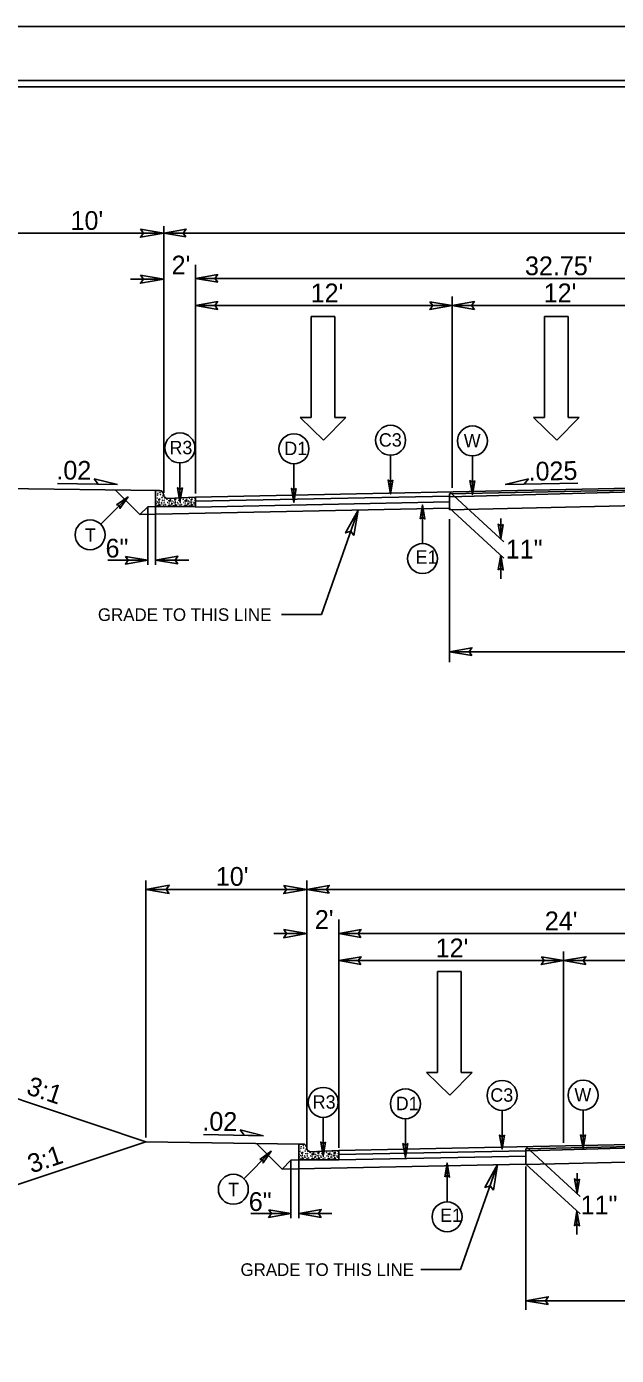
# Model space of a CAD drawing. Extents: x 958711 to 962106, y 831169 to 840840.
# Drawn here: x 959156 to 959402, y 839063 to 839615 of the extents above; entities that cross this region are included whole.
import ezdxf

# ---------------------------------------------------------------- set-up
doc = ezdxf.new("R2010")
doc.units = 0
for name, color, linetype in [('Old_Level_1', 7, 'Continuous'), ('Old_Level_11', 7, 'Continuous'), ('Old_Level_3', 7, 'Continuous'), ('Prop Dimension Text', 7, 'Continuous'), ('Prop Lane Arrow CELL', 7, 'Continuous'), ('Sheet Plot Border Inside CELL', 7, 'Continuous'), ('Sheet Plot Border Outside CELL', 7, 'Continuous'), ('Sheet Typical CELL', 7, 'Continuous'), ('Typical ID Circle CELL', 7, 'Continuous'), ('Typical Terminator CELL', 7, 'Continuous'), ('Typical Text ID Circle CELL', 7, 'Continuous')]:
    doc.layers.add(name, color=color, linetype=linetype)

# ---------------------------------------------------------------- blocks, each defined once
blk = doc.blocks.new('Lane Arrow Through')
at = {"layer": 'Prop Lane Arrow CELL'}
for p, q in [((-3.15, 1.6), (-3.15, 3.1)), ((-3.15, 3.1), (0, 0)), ((-17.15, 1.6), (-3.15, 1.6)), ((-17.15, -1.7), (-17.15, 1.6)), ((0, 0), (-3.15, -3.2)), ((-3.15, -1.7), (-17.15, -1.7)), ((-3.15, -3.2), (-3.15, -1.7))]:
    blk.add_line(p, q, dxfattribs=at)

msp = doc.modelspace()

# ---------------------------------------------------------------- linework, layer by layer
at = {"layer": 'Old_Level_1'}
for p, q in [((959146.5, 839529.55), (959213.41, 839529.55)), ((959213.41, 839421.58), (959213.41, 839532.49)), ((959213.41, 839529.55), (959779.86, 839529.55)), ((959226.62, 839421.34), (959226.62, 839516.32)), ((959199.59, 839510.4), (959213.41, 839510.4)), ((959226.62, 839510.66), (959494.95, 839510.66)), ((959333.31, 839423.65), (959333.31, 839503.17)), ((959226.62, 839499.42), (959333.31, 839499.42)), ((959333.31, 839499.42), (959426.79, 839499.42)), ((959146.5, 839423.43), (959210.34, 839422.49)), ((959169.25, 839425.52), (959194.22, 839425.02)), ((959203.5, 839412.54), (959193.39, 839422.65)), ((959494.95, 839425.26), (959226.62, 839419.83)), ((959494.95, 839424.4), (959332.23, 839419.96)), ((959494.94, 839424.4), (959332.23, 839421.1)), ((959385.49, 839425.61), (959355.28, 839425)), ((959332.23, 839420.24), (959226.62, 839418.11)), ((959332.23, 839417.81), (959226.62, 839415.68)), ((959332.23, 839421.97), (959354.74, 839401.25)), ((959332.23, 839419.96), (959332.23, 839421.1)), ((959332.23, 839419.96), (959332.23, 839414.51)), ((959206.75, 839415.78), (959203.5, 839412.54)), ((959332.23, 839415.14), (959203.5, 839412.54)), ((959210.05, 839415.85), (959206.75, 839415.78)), ((959206.75, 839391.63), (959206.75, 839415.59)), ((959210.05, 839391.63), (959210.05, 839415.59)), ((959278.98, 839371.05), (959294.19, 839414.37)), ((959332.23, 839415.14), (959354.74, 839394.43)), ((959332.23, 839410.67), (959332.23, 839351.24)), ((959353.47, 839410.92), (959353.47, 839402.42)), ((959353.47, 839395.6), (959353.47, 839385.82)), ((959190.15, 839393.59), (959206.75, 839393.59)), ((959210.05, 839393.59), (959223.78, 839393.59)), ((959262.36, 839371.05), (959278.98, 839371.05)), ((959332.23, 839355.52), (959653.23, 839355.52)), ((959206.03, 839153.57), (959206.03, 839260.43)), ((959272.95, 839149.54), (959272.95, 839260.46)), ((959206.03, 839256.74), (959272.95, 839256.74)), ((959272.95, 839256.74), (959716.13, 839256.74)), ((959286.16, 839149.31), (959286.16, 839244.28)), ((959259.12, 839238.36), (959272.95, 839238.36)), ((959286.16, 839238.36), (959473.12, 839238.36)), ((959379.64, 839151.35), (959379.64, 839230.87)), ((959286.16, 839227.12), (959379.64, 839227.12)), ((959379.64, 839227.12), (959473.12, 839227.12)), ((959206.03, 839151.83), (959128.85, 839177.56)), ((959229.94, 839154.84), (959254.92, 839154.34)), ((959473.12, 839152.01), (959286.16, 839148.23)), ((959128.85, 839126.1), (959206.03, 839151.83)), ((959206.03, 839151.83), (959269.87, 839150.89)), ((959262.59, 839140.5), (959251.94, 839151.15)), ((959363.95, 839148.08), (959286.16, 839146.51)), ((959494.54, 839151.58), (959363.95, 839148.03)), ((959473.12, 839151.15), (959363.95, 839148.94)), ((959363.95, 839149.81), (959386.46, 839129.09)), ((959363.95, 839148.03), (959363.95, 839148.94)), ((959363.95, 839148.03), (959363.95, 839142.42)), ((959266.28, 839144.18), (959262.59, 839140.5)), ((959363.95, 839142.55), (959262.59, 839140.5)), ((959269.58, 839144.25), (959266.28, 839144.18)), ((959266.28, 839120.03), (959266.28, 839143.99)), ((959269.58, 839120.03), (959269.58, 839143.99)), ((959363.95, 839145.83), (959286.16, 839144.25)), ((959336.83, 839098.75), (959352.13, 839142.31)), ((959363.95, 839142.55), (959386.46, 839121.83)), ((959363.95, 839141.5), (959363.95, 839082)), ((959385.2, 839138.76), (959385.2, 839130.26)), ((959249.68, 839121.99), (959266.28, 839121.99)), ((959269.58, 839121.99), (959283.31, 839121.99)), ((959385.18, 839123.01), (959385.19, 839113.23)), ((959320.22, 839098.75), (959336.83, 839098.75)), ((959363.95, 839085.77), (959622.89, 839085.77))]:
    msp.add_line(p, q, dxfattribs=at)
for points in [[(959332.23, 839414.51), (959494.95, 839418.21)], [(959363.95, 839142.42), (959494.7, 839145.4)]]:
    msp.add_lwpolyline(points, dxfattribs=at)
at = {"layer": 'Old_Level_11'}
for p, q in [((959186.22, 839425.18), (959184.49, 839427.43)), ((959184.49, 839427.43), (959194.22, 839425.02)), ((959194.22, 839425.02), (959186.22, 839425.18)), ((959355.28, 839425), (959365.04, 839427.43)), ((959363.3, 839425.16), (959355.28, 839425)), ((959365.04, 839427.43), (959363.3, 839425.16)), ((959246.91, 839154.5), (959245.18, 839156.75)), ((959245.18, 839156.75), (959254.92, 839154.34)), ((959254.92, 839154.34), (959246.91, 839154.5))]:
    msp.add_line(p, q, dxfattribs=at)
for points in [[(959203.81, 839531.21), (959213.41, 839529.55), (959203.75, 839527.84), (959204.98, 839529.55)], [(959203.81, 839512.05), (959213.41, 839510.4), (959203.75, 839508.68), (959204.98, 839510.4)], [(959292.49, 839403.78), (959294.19, 839414.37), (959288.98, 839404.92), (959291.18, 839405.6)], [(959215.64, 839255.09), (959206.03, 839256.74), (959215.69, 839258.45), (959214.47, 839256.74)], [(959263.34, 839258.4), (959272.95, 839256.74), (959263.28, 839255.02), (959264.51, 839256.74)], [(959263.34, 839240.02), (959272.95, 839238.36), (959263.28, 839236.65), (959264.51, 839238.36)], [(959350.43, 839131.71), (959352.13, 839142.31), (959346.92, 839132.85), (959349.12, 839133.53)]]:
    msp.add_lwpolyline(points, close=True, dxfattribs=at)
at = {"layer": 'Old_Level_3'}
for p, q in [((959210.05, 839419.17), (959210.05, 839422.2)), ((959210.05, 839415.85), (959210.05, 839419.17)), ((959210.34, 839422.48), (959211.71, 839422.48)), ((959211.32, 839418.93), (959211.32, 839418.35)), ((959211.91, 839418.91), (959211.32, 839418.93)), ((959211.32, 839418.35), (959211.91, 839418.91)), ((959213.5, 839420.44), (959213.39, 839420.29)), ((959213.39, 839420.29), (959213.53, 839420.33)), ((959215.08, 839419.26), (959226.62, 839419.83)), ((959215.08, 839419.26), (959215.08, 839419.26)), ((959215.54, 839418.53), (959215.63, 839418.04)), ((959216.37, 839418.3), (959215.54, 839418.53)), ((959215.63, 839418.04), (959216.37, 839418.3)), ((959218.05, 839418.93), (959218.05, 839418.35)), ((959218.64, 839418.91), (959218.05, 839418.93)), ((959218.05, 839418.35), (959218.64, 839418.91)), ((959222.27, 839418.53), (959222.37, 839418.04)), ((959223.1, 839418.3), (959222.27, 839418.53)), ((959222.37, 839418.04), (959223.1, 839418.3)), ((959224.78, 839418.93), (959224.78, 839418.35)), ((959225.36, 839418.91), (959224.78, 839418.93)), ((959224.78, 839418.35), (959225.36, 839418.91)), ((959226.62, 839419.83), (959226.62, 839415.85)), ((959226.62, 839415.85), (959210.05, 839415.85)), ((959211.24, 839416.23), (959211.7, 839416.88)), ((959211.87, 839416.27), (959211.24, 839416.23)), ((959211.7, 839416.88), (959211.87, 839416.27)), ((959215.35, 839415.96), (959215.69, 839416.57)), ((959216.25, 839416.18), (959215.35, 839415.96)), ((959215.69, 839416.57), (959216.25, 839416.18)), ((959217.97, 839416.23), (959218.43, 839416.88)), ((959218.6, 839416.27), (959217.97, 839416.23)), ((959218.43, 839416.88), (959218.6, 839416.27)), ((959222.08, 839415.96), (959222.42, 839416.57)), ((959222.98, 839416.18), (959222.08, 839415.96)), ((959222.42, 839416.57), (959222.98, 839416.18)), ((959224.69, 839416.23), (959225.15, 839416.88)), ((959225.34, 839416.27), (959224.69, 839416.23)), ((959225.15, 839416.88), (959225.34, 839416.27)), ((959269.58, 839147.57), (959269.58, 839150.6)), ((959269.58, 839144.25), (959269.58, 839147.57)), ((959269.87, 839150.88), (959271.24, 839150.88)), ((959270.86, 839147.33), (959270.86, 839146.75)), ((959271.44, 839147.31), (959270.86, 839147.33)), ((959270.86, 839146.75), (959271.44, 839147.31)), ((959273.03, 839148.84), (959272.92, 839148.69)), ((959272.92, 839148.69), (959273.07, 839148.73)), ((959274.62, 839147.66), (959286.16, 839148.23)), ((959274.62, 839147.66), (959274.62, 839147.66)), ((959275.08, 839146.93), (959275.17, 839146.44)), ((959275.9, 839146.7), (959275.08, 839146.93)), ((959275.17, 839146.44), (959275.9, 839146.7)), ((959277.59, 839147.33), (959277.59, 839146.75)), ((959278.17, 839147.31), (959277.59, 839147.33)), ((959277.59, 839146.75), (959278.17, 839147.31)), ((959281.8, 839146.93), (959281.9, 839146.44)), ((959282.64, 839146.7), (959281.8, 839146.93)), ((959281.9, 839146.44), (959282.64, 839146.7)), ((959284.32, 839147.33), (959284.32, 839146.75)), ((959284.9, 839147.31), (959284.32, 839147.33)), ((959284.32, 839146.75), (959284.9, 839147.31)), ((959286.16, 839148.23), (959286.16, 839144.25)), ((959286.16, 839144.25), (959269.58, 839144.25)), ((959270.77, 839144.63), (959271.24, 839145.28)), ((959271.41, 839144.67), (959270.77, 839144.63)), ((959271.24, 839145.28), (959271.41, 839144.67)), ((959274.89, 839144.36), (959275.23, 839144.97)), ((959275.78, 839144.58), (959274.89, 839144.36)), ((959275.23, 839144.97), (959275.78, 839144.58)), ((959277.5, 839144.63), (959277.96, 839145.28)), ((959278.14, 839144.67), (959277.5, 839144.63)), ((959277.96, 839145.28), (959278.14, 839144.67)), ((959281.62, 839144.36), (959281.96, 839144.97)), ((959282.52, 839144.58), (959281.62, 839144.36)), ((959281.96, 839144.97), (959282.52, 839144.58)), ((959284.23, 839144.63), (959284.69, 839145.28)), ((959284.87, 839144.67), (959284.23, 839144.63)), ((959284.69, 839145.28), (959284.87, 839144.67))]:
    msp.add_line(p, q, dxfattribs=at)
for centre in [(959210.11, 839420.75), (959210.2, 839418.17), (959210.31, 839417.1), (959210.74, 839419.37), (959210.87, 839420.66), (959210.9, 839417.77), (959211.02, 839421.4), (959211.42, 839417.31), (959211.67, 839417.86), (959211.88, 839421.77), (959212.04, 839420.84), (959212.47, 839417.52), (959212.68, 839419.55), (959212.96, 839418.44), (959212.99, 839421.64), (959213.02, 839420.35), (959213.57, 839417.44), (959213.67, 839417.71), (959213.7, 839418.51), (959213.79, 839419.52), (959214.77, 839418.91), (959215.05, 839417.55), (959215.7, 839417.28), (959216.22, 839418.75), (959216.74, 839417.28), (959216.93, 839418.17), (959217.04, 839417.1), (959217.63, 839417.77), (959218.15, 839417.31), (959218.39, 839417.86), (959219.19, 839417.52), (959219.69, 839418.44), (959220.3, 839417.44), (959220.39, 839417.71), (959220.43, 839418.51), (959221.5, 839418.91), (959221.78, 839417.55), (959222.42, 839417.28), (959222.95, 839418.75), (959223.47, 839417.28), (959223.66, 839418.17), (959223.77, 839417.1), (959224.2, 839419.37), (959224.35, 839417.77), (959224.88, 839417.31), (959225.12, 839417.86), (959225.92, 839417.52), (959226.14, 839419.55), (959226.42, 839418.44), (959210.23, 839415.99), (959210.74, 839416.24), (959212.62, 839416.97), (959213.42, 839416.51), (959214.1, 839416.67), (959216.65, 839416.76), (959216.96, 839415.99), (959217.47, 839416.24), (959219.35, 839416.97), (959220.15, 839416.51), (959220.83, 839416.67), (959223.38, 839416.76), (959223.69, 839415.99), (959224.2, 839416.24), (959226.08, 839416.97), (959269.64, 839149.15), (959269.73, 839146.57), (959270.28, 839147.77), (959270.4, 839149.06), (959270.56, 839149.8), (959271.42, 839150.17), (959271.57, 839149.24), (959272.22, 839147.95), (959272.49, 839146.85), (959272.52, 839150.04), (959272.55, 839148.75), (959273.23, 839146.91), (959273.32, 839147.92), (959274.31, 839147.31), (959275.75, 839147.15), (959276.46, 839146.57), (959279.22, 839146.85), (959279.96, 839146.91), (959281.04, 839147.31), (959282.48, 839147.15), (959283.19, 839146.57), (959283.74, 839147.77), (959285.67, 839147.95), (959285.95, 839146.85), (959269.76, 839144.39), (959269.85, 839145.5), (959270.28, 839144.64), (959270.43, 839146.17), (959270.95, 839145.71), (959271.2, 839146.26), (959272, 839145.92), (959272.15, 839145.38), (959272.95, 839144.91), (959273.11, 839145.84), (959273.2, 839146.11), (959273.63, 839145.07), (959274.58, 839145.95), (959275.23, 839145.68), (959276.18, 839145.16), (959276.28, 839145.68), (959276.49, 839144.39), (959276.58, 839145.5), (959277.01, 839144.64), (959277.16, 839146.17), (959277.68, 839145.71), (959277.93, 839146.26), (959278.73, 839145.92), (959278.88, 839145.38), (959279.68, 839144.91), (959279.84, 839145.84), (959279.93, 839146.11), (959280.36, 839145.07), (959281.31, 839145.95), (959281.96, 839145.68), (959282.91, 839145.16), (959283, 839145.68), (959283.22, 839144.39), (959283.3, 839145.5), (959283.74, 839144.64), (959283.89, 839146.17), (959284.41, 839145.71), (959284.66, 839146.26), (959285.46, 839145.92), (959285.61, 839145.38)]:
    msp.add_circle(centre, 0.0432, dxfattribs=at)
for centre, radius, start, end in [((959210.34, 839422.2), 0.287, 90, 180), ((959210.01, 839417.28), 0.0432, 330.4173, 29.5827), ((959210.23, 839422.41), 0.0432, 259.6531, 10.3469), ((959211.71, 839420.83), 1.66, 1.0734, 90), ((959215, 839420.89), 1.64, 181.0734, 272.8624), ((959217.47, 839419.37), 0.0432, 167.7795, 17.938), ((959220.52, 839419.52), 0.0432, 169.8374, 15.8801), ((959269.87, 839150.6), 0.287, 90, 180), ((959269.76, 839150.81), 0.0432, 259.6531, 10.3469), ((959271.24, 839149.23), 1.66, 1.0734, 90), ((959274.53, 839149.29), 1.64, 181.0734, 272.8624), ((959277.01, 839147.77), 0.0432, 167.7795, 17.938), ((959280.05, 839147.92), 0.0432, 169.8374, 15.8801), ((959269.55, 839145.68), 0.0432, 330.4173, 29.5827)]:
    msp.add_arc(centre, radius, start, end, dxfattribs=at)
at = {"layer": 'Sheet Plot Border Inside CELL'}
msp.add_lwpolyline([(960390.3, 839592.94), (958723.8, 839592.94), (958723.8, 838537.84), (960390.3, 838537.84)], close=True, dxfattribs=at)
at = {"layer": 'Sheet Plot Border Outside CELL'}
msp.add_lwpolyline([(960394.8, 839615.39), (958710.8, 839615.39), (958710.8, 838515.39), (960394.8, 838515.39)], close=True, dxfattribs=at)
at = {"layer": 'Sheet Typical CELL'}
msp.add_lwpolyline([(960377.8, 839590.39), (958877.8, 839590.39), (958877.8, 838540.39), (960377.8, 838540.39)], close=True, dxfattribs=at)
at = {"layer": 'Typical ID Circle CELL'}
for p, q in [((959220.17, 839434.02), (959220.17, 839417.93)), ((959267.53, 839433.67), (959267.53, 839417.58)), ((959307.72, 839437.19), (959307.72, 839421.1)), ((959341.74, 839436.93), (959341.74, 839420.84)), ((959187.21, 839408.52), (959198.58, 839419.89)), ((959320.98, 839400.47), (959320.98, 839416.56)), ((959354.05, 839164.89), (959354.05, 839148.8)), ((959387.74, 839164.99), (959387.74, 839148.91)), ((959279.71, 839161.98), (959279.71, 839145.9)), ((959313.86, 839161.37), (959313.86, 839145.28)), ((959246.74, 839136.48), (959258.12, 839147.86)), ((959331.19, 839126.86), (959331.19, 839142.94))]:
    msp.add_line(p, q, dxfattribs=at)
for centre in [(959220.17, 839440.24), (959267.53, 839439.89), (959307.72, 839443.41), (959341.74, 839443.15), (959182.81, 839404.12), (959320.98, 839394.25), (959279.71, 839168.21), (959354.05, 839171.11), (959387.74, 839171.22), (959313.86, 839167.59), (959242.34, 839132.08), (959331.19, 839120.63)]:
    msp.add_circle(centre, 6.23, dxfattribs=at)
at = {"layer": 'Typical Terminator CELL'}
for points in [[(959222.64, 839527.96), (959213.41, 839529.55), (959222.69, 839531.19), (959221.51, 839529.55)], [(959235.85, 839509.08), (959226.62, 839510.66), (959235.9, 839512.3), (959234.72, 839510.66)], [(959235.85, 839497.83), (959226.62, 839499.42), (959235.9, 839501.06), (959234.72, 839499.42)], [(959324.09, 839501.01), (959333.31, 839499.42), (959324.04, 839497.78), (959325.22, 839499.42)], [(959342.53, 839497.83), (959333.31, 839499.42), (959342.58, 839501.06), (959341.41, 839499.42)], [(959221.16, 839423.69), (959220.17, 839417.93), (959219.15, 839423.72), (959220.17, 839422.99)], [(959268.52, 839423.34), (959267.53, 839417.58), (959266.5, 839423.38), (959267.53, 839422.64)], [(959308.71, 839426.87), (959307.72, 839421.1), (959306.7, 839426.9), (959307.72, 839426.16)], [(959342.73, 839426.6), (959341.74, 839420.84), (959340.71, 839426.64), (959341.74, 839425.9)], [(959193.8, 839416.52), (959198.58, 839419.89), (959195.21, 839415.07), (959195, 839416.32)], [(959319.99, 839410.79), (959320.98, 839416.56), (959322.01, 839410.76), (959320.98, 839411.5)], [(959354.52, 839408.48), (959353.47, 839402.42), (959352.4, 839408.52), (959353.47, 839407.74)], [(959197.52, 839395.18), (959206.75, 839393.59), (959197.47, 839391.95), (959198.65, 839393.59)], [(959219.27, 839392), (959210.05, 839393.59), (959219.32, 839395.23), (959218.14, 839393.59)], [(959352.42, 839389.54), (959353.47, 839395.6), (959354.55, 839389.5), (959353.47, 839390.28)], [(959341.46, 839353.93), (959332.23, 839355.52), (959341.51, 839357.16), (959340.33, 839355.52)], [(959282.17, 839255.15), (959272.95, 839256.74), (959282.22, 839258.38), (959281.04, 839256.74)], [(959295.38, 839236.78), (959286.16, 839238.36), (959295.43, 839240), (959294.25, 839238.36)], [(959295.38, 839225.53), (959286.16, 839227.12), (959295.43, 839228.76), (959294.25, 839227.12)], [(959370.41, 839228.71), (959379.64, 839227.12), (959370.36, 839225.48), (959371.54, 839227.12)], [(959370.41, 839228.71), (959379.64, 839227.12), (959370.36, 839225.48), (959371.54, 839227.12)], [(959388.86, 839225.53), (959379.64, 839227.12), (959388.91, 839228.76), (959387.73, 839227.12)], [(959355.04, 839154.57), (959354.05, 839148.8), (959353.02, 839154.6), (959354.05, 839153.86)], [(959388.73, 839154.67), (959387.74, 839148.91), (959386.71, 839154.7), (959387.74, 839153.96)], [(959253.34, 839144.49), (959258.12, 839147.86), (959254.74, 839143.04), (959254.54, 839144.28)], [(959280.7, 839151.66), (959279.71, 839145.9), (959278.68, 839151.69), (959279.71, 839150.96)], [(959314.85, 839151.04), (959313.86, 839145.28), (959312.83, 839151.08), (959313.86, 839150.34)], [(959330.2, 839137.18), (959331.19, 839142.94), (959332.21, 839137.15), (959331.19, 839137.88)], [(959386.24, 839136.32), (959385.2, 839130.26), (959384.12, 839136.36), (959385.2, 839135.58)], [(959257.06, 839123.58), (959266.28, 839121.99), (959257.01, 839120.35), (959258.19, 839121.99)], [(959278.81, 839120.4), (959269.58, 839121.99), (959278.86, 839123.63), (959277.68, 839121.99)], [(959384.14, 839116.94), (959385.18, 839123.01), (959386.26, 839116.91), (959385.18, 839117.68)], [(959373.17, 839084.18), (959363.95, 839085.77), (959373.22, 839087.41), (959372.05, 839085.77)]]:
    msp.add_lwpolyline(points, close=True, dxfattribs=at)

# ---------------------------------------------------------------- block references
at = {"layer": 'Old_Level_1', "xscale": 3, "yscale": 3, "rotation": -90.00000000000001}
for p in [(959279.78, 839443.45), (959376.76, 839443.45), (959332.29, 839171.15)]:
    msp.add_blockref('Lane Arrow Through', p, dxfattribs=at)

# ---------------------------------------------------------------- texts
at = {"layer": 'Old_Level_1'}
for p in [(959186.05, 839368.32), (959245.33, 839096.05)]:
    msp.add_text('GRADE TO THIS LINE', height=5.2473, dxfattribs=at).set_placement(p)
at = {"layer": 'Old_Level_3'}
for s, p in [("10'", (959174.67, 839530.88)), ("2'", (959216.68, 839512.35)), ("10'", (959235.07, 839258.23)), ("2'", (959276.22, 839240.32))]:
    msp.add_text(s, height=7.801, dxfattribs=at).set_placement(p)
for s, rotation, p in [('.02', 359.4336, (959168.75, 839427.14)), ('3:1', 341.5652, (959155.85, 839171.79)), ('.02', 359.4336, (959229.44, 839156.46)), ('3:1', 18.4348, (959158.43, 839138.62))]:
    msp.add_text(s, height=7.801, rotation=rotation, dxfattribs=at).set_placement(p)
at = {"layer": 'Prop Dimension Text'}
for s, rotation, p in [("32.75'", 0, (959363.57, 839512.04)), ("12'", 0, (959274.48, 839500.78)), ("12'", 0, (959371.36, 839500.8)), ('.025', 1.1839, (959365.15, 839426.58)), ('6"', 0, (959189.22, 839394.67)), ('11"', 0, (959355.59, 839394.27)), ("24'", 0, (959371.82, 839239.74)), ("12'", 0, (959326.46, 839228.5)), ('6"', 0, (959248.76, 839123.07)), ('11"', 0, (959386.7, 839121.67))]:
    msp.add_text(s, height=7.801, rotation=rotation, dxfattribs=at).set_placement(p)
at = {"layer": 'Typical Text ID Circle CELL'}
for s, height, p in [('C3', 5.572, (959302.83, 839440.78)), ('W', 5.57, (959338.12, 839440.52)), ('R3', 5.572, (959215.79, 839437.61)), ('D1', 5.572, (959263.54, 839437.26)), ('E1', 5.572, (959318.1, 839392.11)), ('C3', 5.572, (959349.16, 839168.48)), ('W', 5.57, (959384.12, 839168.59)), ('R3', 5.572, (959275.33, 839165.58)), ('D1', 5.572, (959309.86, 839164.96)), ('E1', 5.572, (959328.3, 839118.5))]:
    msp.add_text(s, height=height, dxfattribs=at).set_placement(p)
for p in [(959180.65, 839401.22), (959240.19, 839129.19)]:
    msp.add_text('T', height=5.57, rotation=360, dxfattribs=at).set_placement(p)

doc.saveas('drawing.dxf')
